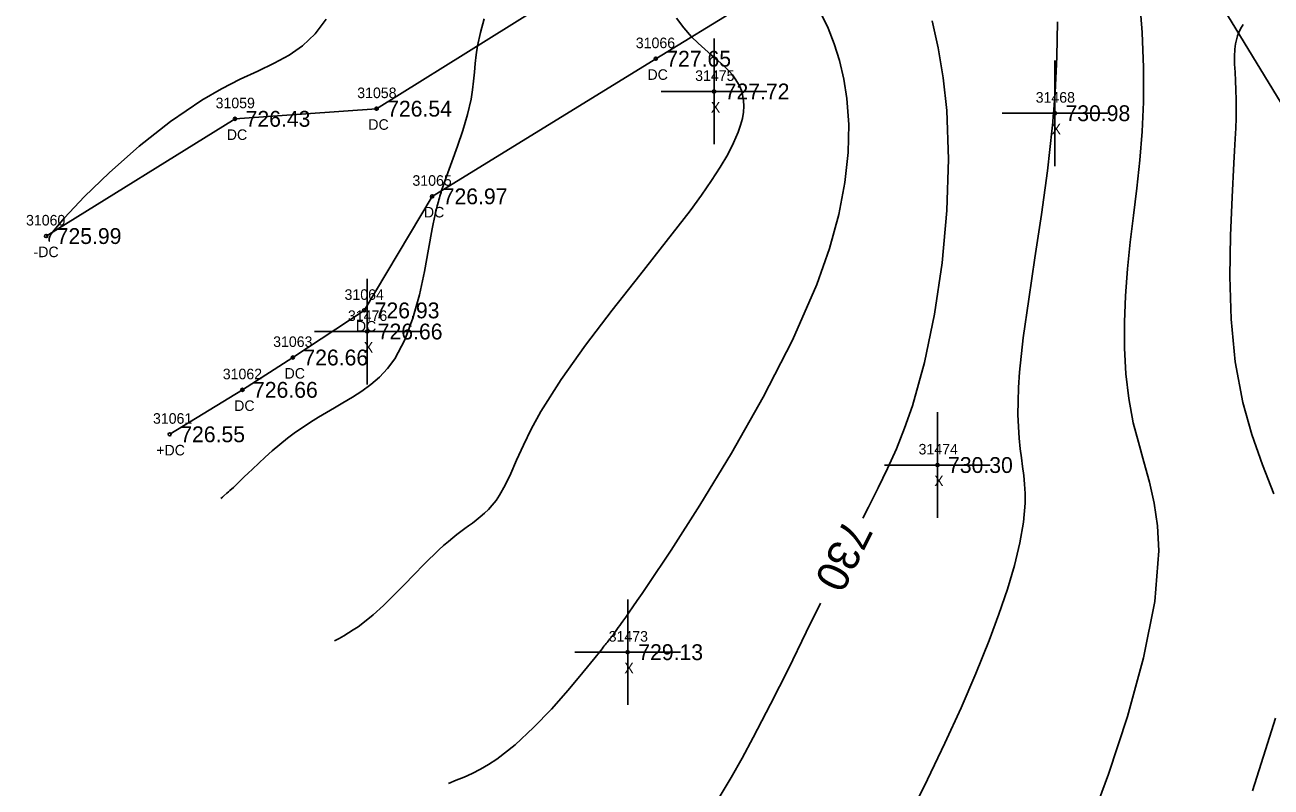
# Model space of a CAD drawing. Extents: x 1376587 to 1378239, y 1000335 to 1003031.
# Drawn here: x 1377628.5 to 1377746.5, y 1000947.5 to 1001019.6 of the extents above; entities that cross this region are included whole.
import ezdxf

# ---------------------------------------------------------------- set-up
doc = ezdxf.new("R2010")
doc.units = 0
for name, color, linetype in [('RD_DTM_Major1', 7, 'Continuous'), ('RD_DTM_Major1_Lbl', 7, 'Continuous'), ('RD_DTM_Minor1', 7, 'Continuous'), ('RD_EX_Conc', 7, 'Continuous'), ('RD_EX_Conc_txCode', 7, 'Continuous'), ('RD_EX_Misc', 7, 'Continuous'), ('RD_EX_Misc_txCode', 7, 'Continuous'), ('RD_EX_Road', 7, 'Continuous'), ('RD_EX_TX_Conc_ELEV', 7, 'Continuous'), ('RD_EX_TX_Misc_ELEV', 7, 'Continuous'), ('RD_SMD_Locator', 7, 'Continuous')]:
    doc.layers.add(name, color=color, linetype=linetype)

msp = doc.modelspace()

# ---------------------------------------------------------------- linework, layer by layer
at = {"layer": 'RD_DTM_Major1'}
for points in [[(1377714.44, 1001020.03), (1377715.01, 1001017.47), (1377715.48, 1001014.62), (1377715.82, 1001011.52), (1377715.99, 1001006.92), (1377715.83, 1001002.05), (1377715.37, 1000997.11), (1377714.65, 1000992.26), (1377713.7, 1000987.68), (1377712.56, 1000983.55), (1377711.82, 1000981.44), (1377711.04, 1000979.48), (1377710.2, 1000977.62), (1377709.32, 1000975.81), (1377708.39, 1000973.98), (1377707.86, 1000972.94)], [(1377703.86, 1000964.88), (1377702.51, 1000962.12), (1377700.81, 1000958.67), (1377699.13, 1000955.32), (1377697.49, 1000952.16), (1377696.43, 1000950.21), (1377695.39, 1000948.37), (1377694.36, 1000946.65), (1377693.34, 1000945.03), (1377692.32, 1000943.5), (1377691.28, 1000942.05), (1377690.25, 1000940.72), (1377689.19, 1000939.47), (1377688.12, 1000938.33), (1377687.02, 1000937.32), (1377685.89, 1000936.46), (1377684.73, 1000935.76), (1377683.87, 1000935.37), (1377682.98, 1000935.06), (1377682.09, 1000934.81), (1377681.2, 1000934.62), (1377680.29, 1000934.46), (1377679.39, 1000934.32)]]:
    msp.add_lwpolyline(points, dxfattribs=at)
at = {"layer": 'RD_DTM_Minor1'}
for points in [[(1377734.07, 1001022.15), (1377734.3, 1001018.92), (1377734.44, 1001015.61), (1377734.45, 1001012.31), (1377734.32, 1001009.54), (1377734.1, 1001006.83), (1377733.81, 1001004.19), (1377733.5, 1001001.6), (1377733.19, 1000999.05), (1377732.93, 1000996.53), (1377732.73, 1000993.99), (1377732.63, 1000991.49), (1377732.64, 1000989.02), (1377732.77, 1000986.61), (1377733.05, 1000984.25), (1377733.47, 1000981.97), (1377733.95, 1000980.11), (1377734.48, 1000978.25), (1377735, 1000976.35), (1377735.45, 1000974.35), (1377735.77, 1000972.2), (1377735.89, 1000969.85), (1377735.5, 1000965.04), (1377734.45, 1000959.71), (1377732.93, 1000954.15), (1377731.13, 1000948.68), (1377729.24, 1000943.57)], [(1377672.02, 1001020.22), (1377671.66, 1001018.91), (1377671.37, 1001017.65), (1377671.24, 1001016.81), (1377671.15, 1001015.98), (1377671.08, 1001015.15), (1377671, 1001014.31), (1377670.91, 1001013.47), (1377670.77, 1001012.59), (1377670.43, 1001011.14), (1377669.99, 1001009.65), (1377669.47, 1001008.15), (1377668.94, 1001006.68), (1377668.43, 1001005.27), (1377667.98, 1001003.95), (1377667.93, 1001003.77), (1377667.87, 1001003.6), (1377667.82, 1001003.43), (1377667.77, 1001003.26), (1377667.73, 1001003.08), (1377667.68, 1001002.91), (1377667.57, 1001002.51), (1377667.47, 1001002.09), (1377667.38, 1001001.67), (1377667.28, 1001001.24), (1377667.19, 1001000.79), (1377667.1, 1001000.32), (1377666.75, 1000998.4), (1377666.35, 1000996.28), (1377665.87, 1000994.06), (1377665.27, 1000991.87), (1377664.51, 1000989.82), (1377663.56, 1000988.03), (1377662.87, 1000987.1), (1377662.1, 1000986.29), (1377661.28, 1000985.58), (1377660.41, 1000984.95), (1377659.53, 1000984.38), (1377658.63, 1000983.84), (1377657.85, 1000983.39), (1377657.08, 1000982.94), (1377656.33, 1000982.48), (1377655.58, 1000982.03), (1377654.86, 1000981.56), (1377654.15, 1000981.07), (1377653.38, 1000980.5), (1377652.65, 1000979.91), (1377651.95, 1000979.31), (1377651.28, 1000978.72), (1377650.66, 1000978.13), (1377650.07, 1000977.57), (1377649.67, 1000977.19), (1377649.29, 1000976.83), (1377648.94, 1000976.48), (1377648.59, 1000976.15), (1377648.26, 1000975.84), (1377647.94, 1000975.55), (1377647.8, 1000975.42), (1377647.65, 1000975.29), (1377647.36, 1000975.04), (1377647.22, 1000974.92), (1377647.08, 1000974.79)], [(1377690.22, 1001020.27), (1377690.9, 1001019.35), (1377691.64, 1001018.51), (1377692.26, 1001017.89), (1377692.89, 1001017.32), (1377693.52, 1001016.77), (1377694.13, 1001016.26), (1377694.7, 1001015.75), (1377695.21, 1001015.24), (1377695.51, 1001014.89), (1377695.78, 1001014.54), (1377696.01, 1001014.17), (1377696.21, 1001013.8), (1377696.36, 1001013.41), (1377696.48, 1001013.01), (1377696.57, 1001012.49), (1377696.59, 1001011.95), (1377696.55, 1001011.38), (1377696.46, 1001010.78), (1377696.29, 1001010.15), (1377696.07, 1001009.48), (1377695.63, 1001008.46), (1377695.07, 1001007.35), (1377694.37, 1001006.17), (1377693.54, 1001004.89), (1377692.58, 1001003.52), (1377691.5, 1001002.04), (1377689.24, 1000999.11), (1377686.74, 1000995.94), (1377684.14, 1000992.63), (1377681.6, 1000989.3), (1377679.29, 1000986.06), (1377677.36, 1000983.02), (1377676.47, 1000981.37), (1377675.72, 1000979.84), (1377675.08, 1000978.43), (1377674.52, 1000977.17), (1377673.99, 1000976.06), (1377673.47, 1000975.11), (1377673.13, 1000974.6), (1377672.77, 1000974.16), (1377672.41, 1000973.75), (1377672.03, 1000973.39), (1377671.64, 1000973.05), (1377671.24, 1000972.74), (1377670.89, 1000972.47), (1377670.53, 1000972.21), (1377670.17, 1000971.94), (1377669.8, 1000971.66), (1377669.43, 1000971.38), (1377669.05, 1000971.08), (1377668.62, 1000970.72), (1377668.17, 1000970.34), (1377667.72, 1000969.93), (1377667.26, 1000969.49), (1377666.78, 1000969.03), (1377666.29, 1000968.54), (1377665.38, 1000967.6), (1377664.43, 1000966.62), (1377663.46, 1000965.63), (1377662.48, 1000964.67), (1377661.49, 1000963.77), (1377660.52, 1000962.98), (1377660.07, 1000962.65), (1377659.62, 1000962.35), (1377659.17, 1000962.07), (1377658.73, 1000961.8), (1377658.29, 1000961.55), (1377657.85, 1000961.3)], [(1377703.95, 1001020.63), (1377704.58, 1001019.31), (1377705.16, 1001017.85), (1377705.66, 1001016.25), (1377706.06, 1001014.51), (1377706.35, 1001012.65), (1377706.53, 1001010.19), (1377706.47, 1001007.54), (1377706.16, 1001004.7), (1377705.58, 1001001.67), (1377704.71, 1000998.46), (1377703.51, 1000995.04), (1377701.21, 1000989.78), (1377698.44, 1000984.37), (1377695.43, 1000979.08), (1377692.44, 1000974.16), (1377689.7, 1000969.9), (1377687.47, 1000966.54), (1377686.96, 1000965.79), (1377686.5, 1000965.13), (1377686.1, 1000964.54), (1377685.74, 1000964.03), (1377685.42, 1000963.57), (1377685.14, 1000963.17), (1377684.99, 1000962.96), (1377684.84, 1000962.76), (1377684.71, 1000962.57), (1377684.58, 1000962.38), (1377684.45, 1000962.21), (1377684.32, 1000962.04), (1377684.24, 1000961.93), (1377684.16, 1000961.82), (1377684.08, 1000961.72), (1377684, 1000961.61), (1377683.91, 1000961.49), (1377683.82, 1000961.38), (1377683.74, 1000961.28), (1377683.66, 1000961.17), (1377683.57, 1000961.06), (1377683.48, 1000960.95), (1377683.38, 1000960.83), (1377683.29, 1000960.7), (1377683.17, 1000960.56), (1377683.05, 1000960.41), (1377682.92, 1000960.25), (1377682.79, 1000960.09), (1377682.65, 1000959.91), (1377682.51, 1000959.73), (1377681.35, 1000958.31), (1377679.95, 1000956.64), (1377678.37, 1000954.86), (1377676.68, 1000953.1), (1377674.94, 1000951.47), (1377673.22, 1000950.12), (1377672.43, 1000949.59), (1377671.65, 1000949.15), (1377670.88, 1000948.76), (1377670.12, 1000948.42), (1377669.37, 1000948.11), (1377668.62, 1000947.81)], [(1377657.04, 1001020.19), (1377656.02, 1001018.8), (1377654.81, 1001017.64), (1377653.55, 1001016.77), (1377652.14, 1001016), (1377650.59, 1001015.26), (1377648.92, 1001014.48), (1377647.14, 1001013.59), (1377645.26, 1001012.52), (1377642.3, 1001010.5), (1377639.33, 1001008.14), (1377636.54, 1001005.67), (1377634.13, 1001003.35), (1377632.26, 1001001.38), (1377631.14, 1001000.02), (1377631.02, 1000999.85), (1377630.94, 1000999.71), (1377630.88, 1000999.59), (1377630.84, 1000999.49), (1377630.82, 1000999.4), (1377630.81, 1000999.33), (1377630.81, 1000999.29), (1377630.81, 1000999.26), (1377630.82, 1000999.23), (1377630.83, 1000999.2), (1377630.83, 1000999.17), (1377630.84, 1000999.15)], [(1377726.3, 1001019.91), (1377726.22, 1001016.62), (1377726.06, 1001013.24), (1377726.03, 1001012.68), (1377725.99, 1001012.12), (1377725.94, 1001011.55), (1377725.9, 1001010.99), (1377725.85, 1001010.42), (1377725.8, 1001009.85), (1377725.34, 1001005.81), (1377724.77, 1001001.68), (1377724.16, 1000997.59), (1377723.57, 1000993.65), (1377723.06, 1000989.99), (1377722.71, 1000986.74), (1377722.61, 1000985.3), (1377722.56, 1000983.97), (1377722.55, 1000982.74), (1377722.59, 1000981.59), (1377722.66, 1000980.51), (1377722.77, 1000979.48), (1377722.88, 1000978.64), (1377722.99, 1000977.81), (1377723.1, 1000976.98), (1377723.18, 1000976.14), (1377723.23, 1000975.26), (1377723.23, 1000974.34), (1377723.08, 1000972.54), (1377722.73, 1000970.58), (1377722.22, 1000968.46), (1377721.55, 1000966.21), (1377720.75, 1000963.83), (1377719.82, 1000961.35), (1377718.56, 1000958.21), (1377717.16, 1000954.96), (1377715.63, 1000951.61), (1377713.99, 1000948.19), (1377712.27, 1000944.72)], [(1377743.88, 1001019.67), (1377743.63, 1001019.25), (1377743.44, 1001018.84), (1377743.34, 1001018.6), (1377743.27, 1001018.35), (1377743.21, 1001018.1), (1377743.16, 1001017.85), (1377743.12, 1001017.59), (1377743.1, 1001017.33), (1377743.06, 1001016.65), (1377743.07, 1001015.93), (1377743.11, 1001015.15), (1377743.15, 1001014.34), (1377743.19, 1001013.47), (1377743.22, 1001012.55), (1377743.22, 1001011.7), (1377743.21, 1001010.81), (1377743.18, 1001009.85), (1377743.13, 1001008.83), (1377743.07, 1001007.72), (1377743, 1001006.53), (1377742.82, 1001003.32), (1377742.67, 1000999.7), (1377742.62, 1000995.8), (1377742.75, 1000991.77), (1377743.13, 1000987.74), (1377743.83, 1000983.87), (1377744.7, 1000980.84), (1377745.72, 1000977.97), (1377746.79, 1000975.23)], [(1377746.94, 1000953.98), (1377745.99, 1000950.99), (1377744.76, 1000947.12)]]:
    msp.add_lwpolyline(points, dxfattribs=at)
at = {"layer": 'RD_EX_Conc'}
for points in [[(1377711.99, 1001044.74), (1377711.66, 1001044.99), (1377707.98, 1001041.73), (1377704.75, 1001038.32), (1377683.1, 1001024.97), (1377661.82, 1001011.7), (1377648.42, 1001010.74), (1377630.53, 1000999.64)], [(1377642.23, 1000980.87), (1377649.12, 1000985.08), (1377653.89, 1000988.14), (1377660.64, 1000992.6), (1377667.08, 1001003.4), (1377688.25, 1001016.43), (1377709.73, 1001029.59), (1377719.53, 1001031.86), (1377719.6, 1001031.89)]]:
    msp.add_lwpolyline(points, dxfattribs=at)
at = {"layer": 'RD_EX_Misc'}
for p, q in [((1377693.78, 1001008.33), (1377693.78, 1001018.33)), ((1377726.05, 1001006.27), (1377726.05, 1001016.27)), ((1377688.78, 1001013.33), (1377698.78, 1001013.33)), ((1377721.05, 1001011.27), (1377731.05, 1001011.27)), ((1377660.93, 1000985.6), (1377660.93, 1000995.6)), ((1377655.93, 1000990.6), (1377665.93, 1000990.6)), ((1377714.93, 1000972.96), (1377714.93, 1000982.96)), ((1377709.93, 1000977.96), (1377719.93, 1000977.96)), ((1377685.6, 1000955.24), (1377685.6, 1000965.24)), ((1377680.6, 1000960.24), (1377690.6, 1000960.24))]:
    msp.add_line(p, q, dxfattribs=at)
at = {"layer": 'RD_EX_Road'}
msp.add_lwpolyline([(1377883.75, 1000788.5), (1377882.63, 1000790.22), (1377852.26, 1000839.6), (1377828.46, 1000879.31), (1377797, 1000930.66), (1377763.07, 1000986.65), (1377731.87, 1001037.81), (1377700.31, 1001089.98), (1377670.43, 1001138.24), (1377639.73, 1001190.03), (1377611.89, 1001234.23), (1377582.78, 1001282.57), (1377552.22, 1001331.03), (1377522.24, 1001382.35), (1377494.26, 1001430.19), (1377463.17, 1001481.14), (1377433.42, 1001531.29), (1377403.14, 1001580.98), (1377371.36, 1001632.19)], dxfattribs=at)
at = {"layer": 'RD_SMD_Locator'}
for centre in [(1377688.25, 1001016.43), (1377693.78, 1001013.33), (1377648.42, 1001010.74), (1377661.82, 1001011.7), (1377726.05, 1001011.27), (1377667.08, 1001003.4), (1377630.53, 1000999.64), (1377660.64, 1000992.6), (1377660.93, 1000990.6), (1377653.89, 1000988.14), (1377649.12, 1000985.08), (1377642.23, 1000980.87), (1377714.93, 1000977.96), (1377685.6, 1000960.24)]:
    msp.add_circle(centre, 0.15, dxfattribs=at)

# ---------------------------------------------------------------- texts
at = {"layer": 'RD_DTM_Major1_Lbl'}
msp.add_text('730', height=3, rotation=243.5929, dxfattribs=at).set_placement((1377706.21, 1000973.04))
at = {"layer": 'RD_EX_Conc_txCode'}
for s, p in [('31066', (1377686.37, 1001017.43)), ('DC', (1377687.47, 1001014.43)), ('31058', (1377659.99, 1001012.7)), ('31059', (1377646.58, 1001011.74)), ('DC', (1377647.64, 1001008.74)), ('DC', (1377661.04, 1001009.7)), ('31065', (1377665.22, 1001004.4)), ('31060', (1377628.63, 1001000.64)), ('DC', (1377666.3, 1001001.4)), ('-DC', (1377629.34, 1000997.64)), ('31064', (1377658.79, 1000993.6)), ('DC', (1377659.86, 1000990.6)), ('31063', (1377652.03, 1000989.14)), ('31062', (1377647.26, 1000986.08)), ('DC', (1377653.11, 1000986.14)), ('DC', (1377648.34, 1000983.08)), ('31061', (1377640.65, 1000981.87)), ('+DC', (1377640.96, 1000978.87))]:
    msp.add_text(s, height=1, dxfattribs=at).set_placement(p)
at = {"layer": 'RD_EX_Misc_txCode'}
for s, p in [('31475', (1377691.99, 1001014.33)), ('31468', (1377724.23, 1001012.27)), ('X', (1377693.47, 1001011.33)), ('X', (1377725.73, 1001009.27)), ('31476', (1377659.11, 1000991.6)), ('X', (1377660.61, 1000988.6)), ('31474', (1377713.14, 1000978.96)), ('X', (1377714.62, 1000975.96)), ('31473', (1377683.8, 1000961.24)), ('X', (1377685.28, 1000958.24))]:
    msp.add_text(s, height=1, dxfattribs=at).set_placement(p)
at = {"layer": 'RD_EX_TX_Conc_ELEV'}
for s, p in [('727.65', (1377689.25, 1001015.68)), ('726.54', (1377662.82, 1001010.95)), ('726.43', (1377649.42, 1001009.99)), ('726.97', (1377668.08, 1001002.65)), ('725.99', (1377631.53, 1000998.89)), ('726.93', (1377661.64, 1000991.85)), ('726.66', (1377654.89, 1000987.39)), ('726.66', (1377650.12, 1000984.33)), ('726.55', (1377643.23, 1000980.12))]:
    msp.add_text(s, height=1.5, dxfattribs=at).set_placement(p)
at = {"layer": 'RD_EX_TX_Misc_ELEV'}
for s, p in [('727.72', (1377694.78, 1001012.58)), ('730.98', (1377727.05, 1001010.52)), ('726.66', (1377661.93, 1000989.85)), ('730.30', (1377715.93, 1000977.21)), ('729.13', (1377686.6, 1000959.49))]:
    msp.add_text(s, height=1.5, dxfattribs=at).set_placement(p)

doc.saveas('drawing.dxf')
